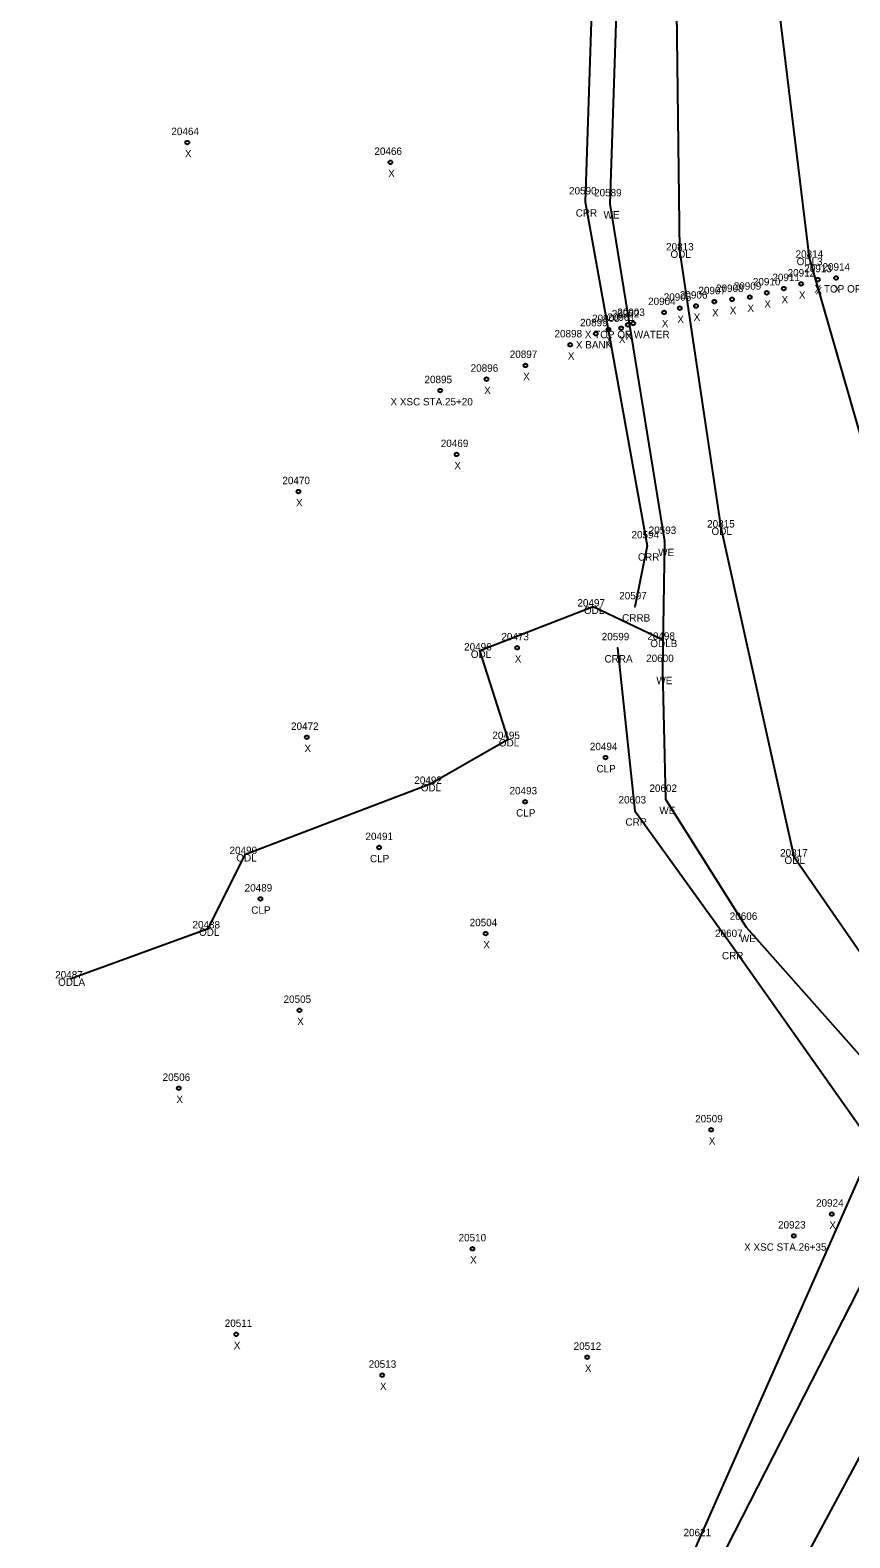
# Model space of a CAD drawing. Extents: x 1965722 to 1969964, y 1117078 to 1118461.
# Drawn here: x 1967715 to 1967825.7, y 1117755.3 to 1117958.8 of the extents above; entities that cross this region are included whole.
import ezdxf

# ---------------------------------------------------------------- set-up
doc = ezdxf.new("R2010")
doc.units = 0
for name, color, linetype in [('RD_EX_H2O', 7, 'Continuous'), ('RD_EX_H2O_txCode', 7, 'Continuous'), ('RD_SMD_Locator', 7, 'Continuous'), ('RD_SMD_Misc', 7, 'Continuous')]:
    doc.layers.add(name, color=color, linetype=linetype)

msp = doc.modelspace()

# ---------------------------------------------------------------- linework, layer by layer
at = {"layer": 'RD_EX_H2O'}
for points in [[(1967848.54, 1118347.45), (1967880.38, 1118337.78), (1967886.93, 1118331.58), (1967896.4, 1118282.85), (1967906.33, 1118232.39), (1967914.38, 1118193.81), (1967904.29, 1118181.59), (1967847.52, 1118139.25), (1967823.99, 1118093.05), (1967800.15, 1118046.69), (1967791.83, 1117992.41), (1967789.93, 1117935.61), (1967798.32, 1117889.19), (1967796.67, 1117880.97)], [(1967849.83, 1118135.18), (1967825.91, 1118086.77), (1967802.99, 1118041.98), (1967795.15, 1117992.28), (1967793.27, 1117935.35), (1967800.64, 1117889.8), (1967800.4, 1117872.52), (1967800.8, 1117854.99), (1967811.67, 1117837.73), (1967837.15, 1117809.04), (1967808.01, 1117752.12), (1967788.48, 1117706.78), (1967783.36, 1117689.17), (1967764.63, 1117648.93), (1967738.42, 1117613.44), (1967731.11, 1117607.31), (1967718.77, 1117573.47), (1967736.01, 1117517.29), (1967781.71, 1117484.69), (1967799.34, 1117478.73), (1967814.43, 1117469.18)], [(1967837.87, 1118086.59), (1967816.35, 1118042.52), (1967807.65, 1118000.54), (1967802.25, 1117964.95), (1967802.7, 1117929.05), (1967808.24, 1117891.66), (1967818.1, 1117847.27), (1967841.92, 1117812.91), (1967830.83, 1117773.47), (1967807.55, 1117730.13), (1967792.1, 1117688.21), (1967759.2, 1117626.42), (1967746.8, 1117597.58), (1967728.31, 1117575.82), (1967748.97, 1117519.79), (1967787.59, 1117491.86), (1967802.7, 1117484.72), (1967813.63, 1117479.24)], [(1967846.86, 1118079.71), (1967831.29, 1118034.88), (1967818.84, 1117997.76), (1967815.72, 1117964.67), (1967820.18, 1117928.06), (1967829.19, 1117896.79), (1967834.11, 1117854.1), (1967863.47, 1117815.02), (1967842.32, 1117765.95), (1967826.02, 1117725.1), (1967807.77, 1117682.35), (1967775.42, 1117611.81), (1967754.74, 1117587.12), (1967745.94, 1117565.65), (1967761.23, 1117525.28), (1967787.1, 1117502.15), (1967805.18, 1117494.11), (1967821.41, 1117490.36)], [(1967720.54, 1117830.82), (1967739.07, 1117837.57), (1967744.11, 1117847.6), (1967769.01, 1117857.07), (1967779.54, 1117863.12), (1967775.75, 1117875.07), (1967791.02, 1117881), (1967800.46, 1117876.52)], [(1967794.3, 1117875.45), (1967796.63, 1117853.43), (1967809.67, 1117835.4), (1967828.83, 1117808.28), (1967805.08, 1117754.56), (1967786.33, 1117708.04), (1967780.19, 1117689.35), (1967762.68, 1117651.19), (1967736.39, 1117616.3), (1967727.33, 1117611.21), (1967715.04, 1117573.35), (1967731.01, 1117514.73), (1967775.86, 1117468.11), (1967793.29, 1117458.88), (1967816.39, 1117454.18)]]:
    msp.add_lwpolyline(points, dxfattribs=at)
at = {"layer": 'RD_SMD_Locator'}
for centre, radius in [((1967736.25, 1117943.61), 0.25), ((1967763.67, 1117940.94), 0.25), ((1967789.93, 1117935.61), 0.001), ((1967793.27, 1117935.35), 0.001), ((1967802.7, 1117929.05), 0.001), ((1967820.18, 1117928.06), 0.001), ((1967821.35, 1117925.11), 0.25), ((1967823.81, 1117925.33), 0.25), ((1967814.45, 1117923.33), 0.25), ((1967816.76, 1117923.91), 0.25), ((1967819.1, 1117924.53), 0.25), ((1967802.71, 1117921.26), 0.25), ((1967804.91, 1117921.55), 0.25), ((1967807.38, 1117922.14), 0.25), ((1967809.77, 1117922.45), 0.25), ((1967812.16, 1117922.75), 0.25), ((1967795.7, 1117919.01), 0.25), ((1967796.44, 1117919.21), 0.25), ((1967800.6, 1117920.68), 0.25), ((1967791.38, 1117917.82), 0.25), ((1967793.08, 1117918.39), 0.25), ((1967794.82, 1117918.55), 0.25), ((1967787.93, 1117916.32), 0.25), ((1967781.89, 1117913.54), 0.25), ((1967776.63, 1117911.68), 0.25), ((1967770.38, 1117910.14), 0.25), ((1967772.6, 1117901.52), 0.25), ((1967751.24, 1117896.51), 0.25), ((1967808.24, 1117891.66), 0.001), ((1967798.32, 1117889.19), 0.001), ((1967800.64, 1117889.8), 0.001), ((1967791.02, 1117881), 0.001), ((1967796.67, 1117880.97), 0.001), ((1967800.46, 1117876.52), 0.001), ((1967775.75, 1117875.07), 0.001), ((1967780.76, 1117875.44), 0.25), ((1967794.3, 1117875.45), 0.001), ((1967800.4, 1117872.52), 0.001), ((1967752.37, 1117863.36), 0.25), ((1967779.54, 1117863.12), 0.001), ((1967792.7, 1117860.62), 0.25), ((1967769.01, 1117857.07), 0.001), ((1967781.85, 1117854.66), 0.25), ((1967800.8, 1117854.99), 0.001), ((1967796.63, 1117853.43), 0.001), ((1967762.13, 1117848.49), 0.25), ((1967744.11, 1117847.6), 0.001), ((1967818.1, 1117847.27), 0.001), ((1967746.11, 1117841.55), 0.25), ((1967739.07, 1117837.57), 0.001), ((1967811.67, 1117837.73), 0.001), ((1967776.52, 1117836.87), 0.25), ((1967809.67, 1117835.4), 0.001), ((1967720.54, 1117830.82), 0.001), ((1967751.39, 1117826.52), 0.25), ((1967735.1, 1117816), 0.25), ((1967806.95, 1117810.4), 0.25), ((1967823.23, 1117799.03), 0.25), ((1967818.1, 1117796.08), 0.25), ((1967774.73, 1117794.35), 0.25), ((1967742.85, 1117782.8), 0.25), ((1967790.23, 1117779.71), 0.25), ((1967762.56, 1117777.29), 0.25)]:
    msp.add_circle(centre, radius, dxfattribs=at)

# ---------------------------------------------------------------- texts
at = {"layer": 'RD_EX_H2O_txCode'}
for s, p in [('20590', (1967787.77, 1117936.61)), ('20589', (1967791.15, 1117936.35)), ('CRR', (1967788.67, 1117933.61)), ('WE', (1967792.43, 1117933.35)), ('20813', (1967800.87, 1117929.05)), ('ODL', (1967801.46, 1117928.05)), ('20814', (1967818.35, 1117928.06)), ('ODL3', (1967818.49, 1117927.06)), ('20815', (1967806.41, 1117891.66)), ('20594', (1967796.2, 1117890.19)), ('20593', (1967798.52, 1117890.8)), ('ODL', (1967807, 1117890.66)), ('WE', (1967799.8, 1117887.8)), ('CRR', (1967797.07, 1117887.19)), ('20597', (1967794.55, 1117881.97)), ('20497', (1967788.9, 1117881)), ('ODL', (1967789.78, 1117880)), ('CRRB', (1967794.94, 1117878.97)), ('20599', (1967792.18, 1117876.45)), ('20498', (1967798.34, 1117876.52)), ('ODLB', (1967798.74, 1117875.52)), ('20496', (1967773.61, 1117875.07)), ('ODL', (1967774.51, 1117874.07)), ('CRRA', (1967792.56, 1117873.45)), ('20600', (1967798.18, 1117873.52)), ('WE', (1967799.56, 1117870.52)), ('20495', (1967777.42, 1117863.12)), ('ODL', (1967778.3, 1117862.12)), ('20492', (1967766.89, 1117857.07)), ('ODL', (1967767.76, 1117856.07)), ('20602', (1967798.62, 1117855.99)), ('20603', (1967794.45, 1117854.43)), ('WE', (1967799.96, 1117852.99)), ('CRR', (1967795.38, 1117851.43)), ('20490', (1967741.95, 1117847.6)), ('20817', (1967816.26, 1117847.27)), ('ODL', (1967742.86, 1117846.6)), ('ODL', (1967816.85, 1117846.27)), ('20606', (1967809.46, 1117838.73)), ('20488', (1967736.95, 1117837.57)), ('ODL', (1967737.83, 1117836.57)), ('20607', (1967807.48, 1117836.4)), ('WE', (1967810.83, 1117835.73)), ('CRR', (1967808.41, 1117833.4)), ('20487', (1967718.42, 1117830.82)), ('ODLA', (1967718.81, 1117829.82)), ('20621', (1967803.22, 1117755.56))]:
    msp.add_text(s, height=1, dxfattribs=at).set_placement(p)
at = {"layer": 'RD_SMD_Misc'}
for s, p in [('20464', (1967734.1, 1117944.61)), ('X', (1967735.93, 1117941.61)), ('20466', (1967761.5, 1117941.94)), ('X', (1967763.36, 1117938.94)), ('20913', (1967819.52, 1117926.11)), ('20914', (1967821.98, 1117926.33)), ('20910', (1967812.58, 1117924.33)), ('20911', (1967815.21, 1117924.91)), ('20912', (1967817.27, 1117925.53)), ('20905', (1967800.55, 1117922.26)), ('20906', (1967802.73, 1117922.55)), ('20907', (1967805.23, 1117923.14)), ('20908', (1967807.61, 1117923.45)), ('20909', (1967810, 1117923.75)), ('X', (1967818.79, 1117922.53)), ('X TOP OF WATER', (1967820.91, 1117923.37)), ('X', (1967821.04, 1117923.11)), ('X', (1967823.5, 1117923.33)), ('20902', (1967793.54, 1117920.01)), ('20903', (1967794.28, 1117920.21)), ('20904', (1967798.44, 1117921.68)), ('X', (1967807.07, 1117920.14)), ('X', (1967809.46, 1117920.45)), ('X', (1967811.85, 1117920.75)), ('X', (1967814.13, 1117921.33)), ('X', (1967816.45, 1117921.91)), ('20899', (1967789.26, 1117918.82)), ('20900', (1967790.88, 1117919.39)), ('20901', (1967792.94, 1117919.55)), ('X', (1967800.29, 1117918.68)), ('X', (1967802.39, 1117919.26)), ('X', (1967804.59, 1117919.55)), ('20898', (1967785.81, 1117917.32)), ('X TOP OF WATER', (1967789.9, 1117917.21)), ('X', (1967792.76, 1117916.39)), ('X', (1967794.5, 1117916.55)), ('X', (1967795.39, 1117917.01)), ('20897', (1967779.77, 1117914.54)), ('X', (1967787.61, 1117914.32)), ('X BANK', (1967788.7, 1117915.82)), ('20896', (1967774.49, 1117912.68)), ('20895', (1967768.26, 1117911.14)), ('X', (1967781.58, 1117911.54)), ('X XSC STA.25+20', (1967763.67, 1117908.14)), ('X', (1967776.32, 1117909.68)), ('20469', (1967770.46, 1117902.52)), ('X', (1967772.29, 1117899.52)), ('20470', (1967749.08, 1117897.51)), ('X', (1967750.92, 1117894.51)), ('20473', (1967778.64, 1117876.44)), ('X', (1967780.45, 1117873.44)), ('20472', (1967750.25, 1117864.36)), ('X', (1967752.06, 1117861.36)), ('20494', (1967790.58, 1117861.62)), ('CLP', (1967791.47, 1117858.62)), ('20493', (1967779.74, 1117855.66)), ('CLP', (1967780.63, 1117852.66)), ('20491', (1967760.29, 1117849.49)), ('CLP', (1967760.9, 1117846.49)), ('20489', (1967743.99, 1117842.55)), ('CLP', (1967744.88, 1117839.55)), ('20504', (1967774.36, 1117837.87)), ('X', (1967776.2, 1117834.87)), ('20505', (1967749.24, 1117827.52)), ('X', (1967751.08, 1117824.52)), ('20506', (1967732.92, 1117817)), ('X', (1967734.78, 1117814)), ('20509', (1967804.79, 1117811.4)), ('X', (1967806.63, 1117808.4)), ('20924', (1967821.11, 1117800.03)), ('20923', (1967815.98, 1117797.08)), ('X', (1967822.91, 1117797.03)), ('20510', (1967772.86, 1117795.35)), ('X XSC STA.26+35', (1967811.4, 1117794.08)), ('X', (1967774.42, 1117792.35)), ('20511', (1967741.3, 1117783.8)), ('X', (1967742.53, 1117780.8)), ('20512', (1967788.39, 1117780.71)), ('20513', (1967760.73, 1117778.29)), ('X', (1967789.91, 1117777.71)), ('X', (1967762.25, 1117775.29))]:
    msp.add_text(s, height=1, dxfattribs=at).set_placement(p)

doc.saveas('drawing.dxf')
